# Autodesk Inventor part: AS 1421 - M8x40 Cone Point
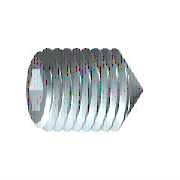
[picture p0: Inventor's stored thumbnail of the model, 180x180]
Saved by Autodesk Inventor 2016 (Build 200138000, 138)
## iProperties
IsCustomPart: 0
Created: 2015-02
Part Number: AS 1421 - M8x40 Cone Point
Material: Steel, Mild
Description: ISO metric hexagon socket set screws
Document SubType Name: Modeling
Standard: AS 1421
Designer: stank
Standards Organization: AS
Language: en-US
Size Designation: M8x40 Cone Point
Categories: <MemberInstance><Categories><Category DisplayName="Fasteners" InternalName="e4da775c-781d-43d5-af7c-5136215cf5a6" Mnemonic="FSTN"><Category DisplayName="Bolts"
Density: 7.85 g/cm^3
Appearance: Semi-Polished
Mass: 14.7089 g
Surface Area: 11.2769 cm^2
Volume: 1.87374 cm^3
Author: stank
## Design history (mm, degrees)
sketch "Sketch1"
  geometry: L1 (0, 0)-(33.667, 0); L2 (40, 2.309)-(40, 4); L3 (40, 4)-(0, 4); L4 (40, 2.309)-(35, 2.309); L5 (35, 2.309)-(33.667, 0); L6 (0, -2.4)-(0, 14.4) reference; L7 (0, 4)-(0, 0)
  constraints: 13 end point, 3 parallel, 1 collinear, 1 perpendicular, 1 point on line
  dimensions: "d0" = 5 distance of L2.start L4.end (= INTI); "d1" = 60 deg angle of L5 L1; "d2" = 8 diameter of L3 L1 (= NND); "d3" = 4.6188 diameter of L4 L1 (= 1.1547 x SW); "d5" = 40 distance from line of L2 L3.end (= NLG)
revolve "Body" sketch "Sketch1" stored, may be unused: angle "d6" = 90 deg
sketch "Sketch2"
  geometry: L1 (-1.155, 2)-(1.155, 2); L2 (1.155, 2)-(2.309, 0); L3 (2.309, 0)-(1.155, -2); L4 (1.155, -2)-(-1.155, -2); L5 (-1.155, -2)-(-2.309, 0); L6 (-2.309, 0)-(-1.155, 2); 3 further points
  constraints: 12 end point, 1 coincident, 1 horizontal, 13 other
extrude "Slot" join sketch "Sketch2" taper "d7" = 0 deg; stored distance "d21" = 10
workaxis "Work Axis1"
workplane "Work Plane1"
body "Solid1"
feature "Thread" dims "d12" = 40 (= NLG), "d13" = 0
chamfer "Chamfer1" distance "d8" = 1.73205 (computed from NND, SPD, FAWI); stored, may be unused: angle "d9" = 60 deg (= FAWI), second distance "d34" = 1.73205 (computed from NND, SPD, FAWI)
chamfer "Chamfer2" distance "d10" = 0.76681 (= -0.5 x GD1 + 0.5 x NND); stored, may be unused: angle "d11" = 60 deg (= FAWI), second distance "d35" = 0.76681 (= -0.5 x GD1 + 0.5 x NND)
other parameters: "NND" = 8 [user parameter; used in 5 equation terms], "NLG" = 40 [user parameter; used in 2 equation terms], "INTI" = 5 [user parameter; used in 1 equation term], "FAWI" = 60 deg [user parameter; used in 4 equation terms], "SW" = 4 [user parameter; used in 2 equation terms], "GD1" = 6.46637 (= THREADDIA - 1.2269 x PTC) [user parameter; used in 2 equation terms], "d4" = 0, "FAWI1" = 45 deg [user parameter], "SPD" = 2 [user parameter; used in 2 equation terms], "d36" = 0, "d37" = 0, "GUL" = 0.76681 (= 0.61345 x PTC) [user parameter], "TPU" = 8 (computed from PTC) [user parameter], "TOA" = 30 deg [user parameter], "THREADDIA" = 8 [user parameter; used in 1 equation term], "PTC" = 1.25 [user parameter; used in 4 equation terms], "GAL" = 0.76681 (= 0.61345 x PTC) [user parameter], "E0" = 4.62 (= 1.155 x SW) [user parameter]
